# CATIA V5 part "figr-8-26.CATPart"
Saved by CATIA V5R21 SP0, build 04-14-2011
Part number: Part3
Bounding box of the stored display mesh (mm): x -50 to 50, y -40 to 40, z 0 to 36
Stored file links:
  D:\CATIA V5R21 E-RESOURCES\CATIA-V5R21\catia-v5r21-prt\c08-catia-v5r20-prt\c08-catia-v5r21-figr-8-26.CATPart
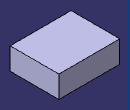
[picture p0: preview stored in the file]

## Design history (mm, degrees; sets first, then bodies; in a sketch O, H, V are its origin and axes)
Body1 (main body)
  Sketch1 on xy-plane, origin (0, 0, 0), H (1, 0, 0), V (0, 1, 0)
    line L1 (-50, 40) -> (50, 40)
    line L2 (50, 40) -> (50, -40)
    line L3 (50, -40) -> (-50, -40)
    line L4 (-50, -40) -> (-50, 40)
    horizontal: L1 H, L3 H
    vertical: L2 V, L4 V
  Pad1: profile Sketch1, direction (0, 0, 1), length 36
